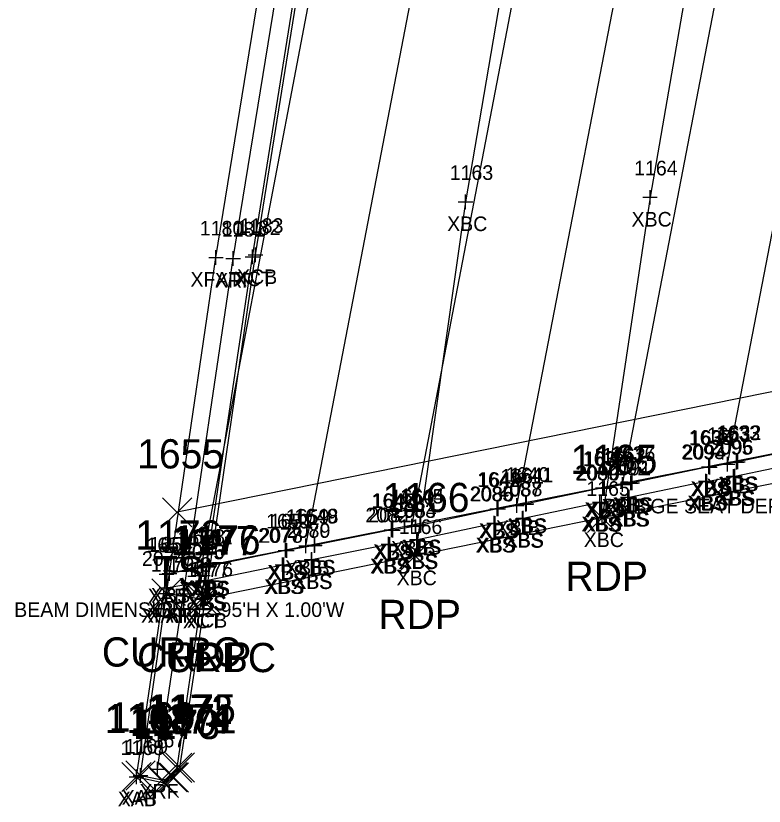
# Model space of a CAD drawing. Extents: x 1683147 to 1683637, y 416837 to 418211.
# Drawn here: x 1683191.5 to 1683242.7, y 417432.4 to 417486.5 of the extents above; entities that cross this region are included whole.
import ezdxf

# ---------------------------------------------------------------- set-up
doc = ezdxf.new("R2010")
doc.units = 0
for name, color, linetype in [('B_A', 7, 'Continuous'), ('B_C', 7, 'Continuous'), ('B_I', 7, 'Continuous'), ('B_TIC', 7, 'Continuous'), ('BB', 7, 'Continuous'), ('BDC', 7, 'Continuous'), ('BELB', 7, 'Continuous'), ('BF', 7, 'Continuous'), ('BR', 7, 'Continuous'), ('BSE', 7, 'Continuous'), ('BSUBM', 7, 'Continuous'), ('L_A', 7, 'Continuous'), ('L_I', 7, 'Continuous'), ('L_TIC', 7, 'Continuous'), ('LELB', 7, 'Continuous'), ('P_A', 7, 'Continuous'), ('P_I', 7, 'Continuous'), ('P_TIC', 7, 'Continuous'), ('PET', 7, 'Continuous'), ('R_A', 7, 'Continuous'), ('R_I', 7, 'Continuous'), ('R_TIC', 7, 'Continuous'), ('RC', 7, 'Continuous')]:
    doc.layers.add(name, color=color, linetype=linetype)

msp = doc.modelspace()

# ---------------------------------------------------------------- linework, layer by layer
at = {"layer": 'B_TIC'}
for p, q in [((1683234.935, 417474.067), (1683235.011, 417474.067)), ((1683222.32, 417473.758), (1683222.395, 417473.758)), ((1683205.244, 417469.957), (1683205.32, 417469.957)), ((1683206.416, 417469.882), (1683206.492, 417469.882)), ((1683207.749, 417469.989), (1683207.825, 417469.989)), ((1683207.946, 417470.136), (1683208.022, 417470.136)), ((1683240.227, 417455.825), (1683240.303, 417455.825)), ((1683240.858, 417455.949), (1683240.934, 417455.949)), ((1683240.939, 417455.968), (1683241.015, 417455.968)), ((1683238.962, 417455.642), (1683239.037, 417455.642)), ((1683239.038, 417455.615), (1683239.113, 417455.615)), ((1683238.747, 417454.66), (1683238.823, 417454.66)), ((1683238.823, 417454.633), (1683238.899, 417454.633)), ((1683240.644, 417454.967), (1683240.72, 417454.967)), ((1683240.729, 417454.99), (1683240.805, 417454.99)), ((1683231.708, 417454.198), (1683231.784, 417454.198)), ((1683231.818, 417454.176), (1683231.894, 417454.176)), ((1683233.059, 417454.423), (1683233.135, 417454.423)), ((1683233.626, 417454.527), (1683233.702, 417454.527)), ((1683233.723, 417454.539), (1683233.799, 417454.539)), ((1683233.417, 417453.549), (1683233.493, 417453.549)), ((1683233.51, 417453.558), (1683233.586, 417453.558)), ((1683225.821, 417452.979), (1683225.896, 417452.979)), ((1683226.435, 417453.076), (1683226.511, 417453.076)), ((1683226.483, 417453.11), (1683226.559, 417453.11)), ((1683231.494, 417453.218), (1683231.57, 417453.218)), ((1683231.605, 417453.195), (1683231.681, 417453.195)), ((1683224.476, 417452.766), (1683224.552, 417452.766)), ((1683224.555, 417452.749), (1683224.631, 417452.749)), ((1683226.223, 417452.096), (1683226.299, 417452.096)), ((1683226.268, 417452.128), (1683226.344, 417452.128)), ((1683231.664, 417452.147), (1683231.74, 417452.147)), ((1683218.643, 417451.571), (1683218.718, 417451.571)), ((1683219.203, 417451.621), (1683219.278, 417451.621)), ((1683219.252, 417451.652), (1683219.327, 417451.652)), ((1683224.267, 417451.789), (1683224.343, 417451.789)), ((1683224.341, 417451.768), (1683224.417, 417451.768)), ((1683217.258, 417451.322), (1683217.334, 417451.322)), ((1683217.34, 417451.308), (1683217.416, 417451.308)), ((1683211.977, 417450.252), (1683212.052, 417450.252)), ((1683212.015, 417450.268), (1683212.09, 417450.268)), ((1683217.043, 417450.341), (1683217.119, 417450.341)), ((1683217.133, 417450.332), (1683217.209, 417450.332)), ((1683218.988, 417450.64), (1683219.064, 417450.64)), ((1683219.037, 417450.671), (1683219.113, 417450.671)), ((1683210.009, 417449.921), (1683210.084, 417449.921)), ((1683210.085, 417449.916), (1683210.16, 417449.916)), ((1683211.401, 417450.232), (1683211.477, 417450.232)), ((1683211.768, 417449.274), (1683211.844, 417449.274)), ((1683211.801, 417449.288), (1683211.877, 417449.288)), ((1683218.866, 417449.537), (1683218.942, 417449.537)), ((1683204.011, 417448.755), (1683204.086, 417448.755)), ((1683204.251, 417448.864), (1683204.327, 417448.864)), ((1683204.726, 417448.785), (1683204.801, 417448.785)), ((1683204.787, 417448.839), (1683204.863, 417448.839)), ((1683209.794, 417448.94), (1683209.87, 417448.94)), ((1683209.876, 417448.939), (1683209.952, 417448.939)), ((1683201.862, 417448.298), (1683201.937, 417448.298)), ((1683201.862, 417448.298), (1683201.937, 417448.298)), ((1683202.059, 417448.337), (1683202.135, 417448.337)), ((1683204.517, 417447.808), (1683204.593, 417447.808)), ((1683204.574, 417447.86), (1683204.65, 417447.86)), ((1683201.846, 417447.358), (1683201.922, 417447.358)), ((1683201.856, 417446.968), (1683201.931, 417446.968)), ((1683201.856, 417446.968), (1683201.931, 417446.968)), ((1683203.022, 417446.95), (1683203.098, 417446.95)), ((1683204.263, 417446.59), (1683204.339, 417446.59)), ((1683204.527, 417446.635), (1683204.602, 417446.635)), ((1683201.253, 417434.944), (1683201.328, 417434.944)), ((1683199.805, 417434.421), (1683199.88, 417434.421)), ((1683200.088, 417434.523), (1683200.163, 417434.523))]:
    msp.add_line(p, q, dxfattribs=at)
for points in [[(1683222.317, 417473.258), (1683222.317, 417474.258)], [(1683234.432, 417474.067), (1683235.432, 417474.067)], [(1683234.932, 417473.567), (1683234.932, 417474.567)], [(1683221.817, 417473.758), (1683222.817, 417473.758)], [(1683205.241, 417469.457), (1683205.241, 417470.457)], [(1683206.413, 417469.382), (1683206.413, 417470.382)], [(1683207.746, 417469.489), (1683207.746, 417470.489)], [(1683207.943, 417469.636), (1683207.943, 417470.636)], [(1683204.741, 417469.957), (1683205.741, 417469.957)], [(1683205.913, 417469.882), (1683206.913, 417469.882)], [(1683207.246, 417469.989), (1683208.246, 417469.989)], [(1683207.443, 417470.136), (1683208.443, 417470.136)], [(1683240.224, 417455.325), (1683240.224, 417456.325)], [(1683240.855, 417455.449), (1683240.855, 417456.449)], [(1683240.936, 417455.468), (1683240.936, 417456.468)], [(1683238.958, 417455.142), (1683238.958, 417456.142)], [(1683239.034, 417455.115), (1683239.034, 417456.115)], [(1683239.724, 417455.825), (1683240.724, 417455.825)], [(1683240.355, 417455.949), (1683241.355, 417455.949)], [(1683240.436, 417455.968), (1683241.436, 417455.968)], [(1683238.458, 417455.642), (1683239.458, 417455.642)], [(1683238.534, 417455.615), (1683239.534, 417455.615)], [(1683238.744, 417454.16), (1683238.744, 417455.16)], [(1683238.82, 417454.133), (1683238.82, 417455.133)], [(1683240.641, 417454.467), (1683240.641, 417455.467)], [(1683240.726, 417454.49), (1683240.726, 417455.49)], [(1683231.705, 417453.698), (1683231.705, 417454.698)], [(1683231.815, 417453.676), (1683231.815, 417454.676)], [(1683233.056, 417453.923), (1683233.056, 417454.923)], [(1683233.623, 417454.027), (1683233.623, 417455.027)], [(1683233.72, 417454.039), (1683233.72, 417455.039)], [(1683238.244, 417454.66), (1683239.244, 417454.66)], [(1683238.32, 417454.633), (1683239.32, 417454.633)], [(1683240.141, 417454.967), (1683241.141, 417454.967)], [(1683240.226, 417454.99), (1683241.226, 417454.99)], [(1683231.205, 417454.198), (1683232.205, 417454.198)], [(1683231.315, 417454.176), (1683232.315, 417454.176)], [(1683232.556, 417454.423), (1683233.556, 417454.423)], [(1683233.123, 417454.527), (1683234.123, 417454.527)], [(1683233.22, 417454.539), (1683234.22, 417454.539)], [(1683233.414, 417453.049), (1683233.414, 417454.049)], [(1683233.507, 417453.058), (1683233.507, 417454.058)], [(1683226.432, 417452.576), (1683226.432, 417453.576)], [(1683226.48, 417452.61), (1683226.48, 417453.61)], [(1683231.491, 417452.718), (1683231.491, 417453.718)], [(1683231.602, 417452.695), (1683231.602, 417453.695)], [(1683232.914, 417453.549), (1683233.914, 417453.549)], [(1683233.007, 417453.558), (1683234.007, 417453.558)], [(1683224.473, 417452.266), (1683224.473, 417453.266)], [(1683224.552, 417452.249), (1683224.552, 417453.249)], [(1683225.317, 417452.979), (1683226.317, 417452.979)], [(1683225.817, 417452.479), (1683225.817, 417453.479)], [(1683225.932, 417453.076), (1683226.932, 417453.076)], [(1683225.98, 417453.11), (1683226.98, 417453.11)], [(1683230.991, 417453.218), (1683231.991, 417453.218)], [(1683231.102, 417453.195), (1683232.102, 417453.195)], [(1683223.973, 417452.766), (1683224.973, 417452.766)], [(1683224.052, 417452.749), (1683225.052, 417452.749)], [(1683226.22, 417451.596), (1683226.22, 417452.596)], [(1683226.265, 417451.628), (1683226.265, 417452.628)], [(1683231.661, 417451.647), (1683231.661, 417452.647)], [(1683218.639, 417451.071), (1683218.639, 417452.071)], [(1683219.199, 417451.121), (1683219.199, 417452.121)], [(1683219.248, 417451.152), (1683219.248, 417452.152)], [(1683224.264, 417451.289), (1683224.264, 417452.289)], [(1683224.338, 417451.268), (1683224.338, 417452.268)], [(1683225.72, 417452.096), (1683226.72, 417452.096)], [(1683225.765, 417452.128), (1683226.765, 417452.128)], [(1683231.161, 417452.147), (1683232.161, 417452.147)], [(1683217.255, 417450.822), (1683217.255, 417451.822)], [(1683217.337, 417450.808), (1683217.337, 417451.808)], [(1683218.139, 417451.571), (1683219.139, 417451.571)], [(1683218.699, 417451.621), (1683219.699, 417451.621)], [(1683218.748, 417451.652), (1683219.748, 417451.652)], [(1683223.764, 417451.789), (1683224.764, 417451.789)], [(1683223.838, 417451.768), (1683224.838, 417451.768)], [(1683216.755, 417451.322), (1683217.755, 417451.322)], [(1683216.837, 417451.308), (1683217.837, 417451.308)], [(1683217.04, 417449.841), (1683217.04, 417450.841)], [(1683217.13, 417449.832), (1683217.13, 417450.832)], [(1683218.985, 417450.14), (1683218.985, 417451.14)], [(1683219.034, 417450.171), (1683219.034, 417451.171)], [(1683210.005, 417449.421), (1683210.005, 417450.421)], [(1683210.081, 417449.416), (1683210.081, 417450.416)], [(1683211.398, 417449.732), (1683211.398, 417450.732)], [(1683211.473, 417450.252), (1683212.473, 417450.252)], [(1683211.511, 417450.268), (1683212.511, 417450.268)], [(1683211.973, 417449.752), (1683211.973, 417450.752)], [(1683212.011, 417449.768), (1683212.011, 417450.768)], [(1683216.54, 417450.341), (1683217.54, 417450.341)], [(1683216.63, 417450.332), (1683217.63, 417450.332)], [(1683218.485, 417450.64), (1683219.485, 417450.64)], [(1683218.534, 417450.671), (1683219.534, 417450.671)], [(1683209.505, 417449.921), (1683210.505, 417449.921)], [(1683209.581, 417449.916), (1683210.581, 417449.916)], [(1683210.898, 417450.232), (1683211.898, 417450.232)], [(1683211.765, 417448.774), (1683211.765, 417449.774)], [(1683211.798, 417448.788), (1683211.798, 417449.788)], [(1683218.863, 417449.037), (1683218.863, 417450.037)], [(1683204.007, 417448.255), (1683204.007, 417449.255)], [(1683204.248, 417448.364), (1683204.248, 417449.364)], [(1683204.722, 417448.285), (1683204.722, 417449.285)], [(1683204.784, 417448.339), (1683204.784, 417449.339)], [(1683209.791, 417448.44), (1683209.791, 417449.44)], [(1683209.873, 417448.439), (1683209.873, 417449.439)], [(1683211.265, 417449.274), (1683212.265, 417449.274)], [(1683211.298, 417449.288), (1683212.298, 417449.288)], [(1683218.363, 417449.537), (1683219.363, 417449.537)], [(1683201.858, 417447.798), (1683201.858, 417448.798)], [(1683201.858, 417447.798), (1683201.858, 417448.798)], [(1683202.056, 417447.837), (1683202.056, 417448.837)], [(1683203.507, 417448.755), (1683204.507, 417448.755)], [(1683203.748, 417448.864), (1683204.748, 417448.864)], [(1683204.222, 417448.785), (1683205.222, 417448.785)], [(1683204.284, 417448.839), (1683205.284, 417448.839)], [(1683209.291, 417448.94), (1683210.291, 417448.94)], [(1683209.373, 417448.939), (1683210.373, 417448.939)], [(1683201.358, 417448.298), (1683202.358, 417448.298)], [(1683201.358, 417448.298), (1683202.358, 417448.298)], [(1683201.556, 417448.337), (1683202.556, 417448.337)], [(1683204.514, 417447.308), (1683204.514, 417448.308)], [(1683204.571, 417447.36), (1683204.571, 417448.36)], [(1683201.843, 417446.858), (1683201.843, 417447.858)], [(1683204.014, 417447.808), (1683205.014, 417447.808)], [(1683204.071, 417447.86), (1683205.071, 417447.86)], [(1683201.343, 417447.358), (1683202.343, 417447.358)], [(1683201.852, 417446.468), (1683201.852, 417447.468)], [(1683201.852, 417446.468), (1683201.852, 417447.468)], [(1683203.019, 417446.45), (1683203.019, 417447.45)], [(1683204.26, 417446.09), (1683204.26, 417447.09)], [(1683204.523, 417446.135), (1683204.523, 417447.135)], [(1683201.352, 417446.968), (1683202.352, 417446.968)], [(1683201.352, 417446.968), (1683202.352, 417446.968)], [(1683202.519, 417446.95), (1683203.519, 417446.95)], [(1683203.76, 417446.59), (1683204.76, 417446.59)], [(1683204.023, 417446.635), (1683205.023, 417446.635)], [(1683201.249, 417434.444), (1683201.249, 417435.444)], [(1683199.801, 417433.921), (1683199.801, 417434.921)], [(1683200.084, 417434.023), (1683200.084, 417435.023)], [(1683200.749, 417434.944), (1683201.749, 417434.944)], [(1683199.301, 417434.421), (1683200.301, 417434.421)], [(1683199.584, 417434.523), (1683200.584, 417434.523)]]:
    msp.add_lwpolyline(points, dxfattribs=at)
at = {"layer": 'BB'}
for points in [[(1683240.224, 417455.825), (1683249.612, 417504.3), (1683268.309, 417601.755), (1683277.362, 417650.167)], [(1683233.056, 417454.423), (1683242.375, 417502.873), (1683260.963, 417600.277), (1683270.09, 417648.672)], [(1683225.817, 417452.979), (1683235.185, 417501.44), (1683252.981, 417597.315), (1683262.91, 417647.271)], [(1683218.639, 417451.571), (1683227.942, 417499.995), (1683246.282, 417596.559), (1683255.565, 417645.821)], [(1683211.398, 417450.232), (1683220.685, 417498.601), (1683239.091, 417595.537), (1683248.339, 417644.482)], [(1683204.248, 417448.864), (1683213.453, 417497.213), (1683232.034, 417594.621), (1683241.123, 417643.096)]]:
    msp.add_lwpolyline(points, dxfattribs=at)
at = {"layer": 'BDC'}
for points in [[(1683204.26, 417446.59), (1683207.746, 417469.989), (1683213.462, 417505.801), (1683221.311, 417549.93), (1683228.046, 417584.722), (1683234.074, 417613.621), (1683241.065, 417645.18)], [(1683204.523, 417446.635), (1683207.943, 417470.136), (1683213.692, 417505.86), (1683221.542, 417549.946), (1683228.342, 417584.807), (1683234.248, 417613.515), (1683241.392, 417644.923)]]:
    msp.add_lwpolyline(points, dxfattribs=at)
at = {"layer": 'BELB'}
for points in [[(1683269.206, 417650.948), (1683260.393, 417611.397), (1683256.447, 417590.785), (1683246.822, 417543.339), (1683241.399, 417511.39), (1683234.932, 417474.067), (1683231.661, 417452.147)], [(1683255.821, 417648.166), (1683248.035, 417613.702), (1683243.06, 417587.805), (1683234.781, 417546.02), (1683228.274, 417508.761), (1683222.317, 417473.758), (1683218.863, 417449.537)]]:
    msp.add_lwpolyline(points, dxfattribs=at)
at = {"layer": 'BF'}
msp.add_lwpolyline([(1683201.852, 417446.968), (1683205.241, 417469.957), (1683210.957, 417505.098), (1683219.149, 417550.319), (1683225.494, 417584.011), (1683231.655, 417613.999), (1683238.79, 417645.736)], dxfattribs=at)
at = {"layer": 'BR'}
msp.add_lwpolyline([(1683201.249, 417434.944), (1683203.019, 417446.95), (1683206.413, 417469.882), (1683212.207, 417505.421), (1683220.042, 417550.002), (1683226.73, 417584.319), (1683232.917, 417613.974), (1683239.772, 417645.191), (1683242.155, 417655.448)], dxfattribs=at)
at = {"layer": 'BSE'}
msp.add_lwpolyline([(1683246.189, 417457.073), (1683240.936, 417455.968), (1683240.855, 417455.949), (1683239.034, 417455.615), (1683238.958, 417455.642), (1683233.72, 417454.539), (1683233.623, 417454.527), (1683231.815, 417454.176), (1683231.705, 417454.198), (1683226.48, 417453.11), (1683226.432, 417453.076), (1683224.552, 417452.749), (1683224.473, 417452.766), (1683219.248, 417451.652), (1683219.199, 417451.621), (1683217.337, 417451.308), (1683217.255, 417451.322), (1683212.011, 417450.268), (1683211.973, 417450.252), (1683210.081, 417449.916), (1683210.005, 417449.921), (1683204.784, 417448.839), (1683204.722, 417448.785), (1683202.056, 417448.337), (1683201.843, 417447.358), (1683204.514, 417447.808), (1683204.571, 417447.86), (1683209.791, 417448.94), (1683209.873, 417448.939), (1683211.765, 417449.274), (1683211.798, 417449.288), (1683217.04, 417450.341), (1683217.13, 417450.332), (1683218.985, 417450.64), (1683219.034, 417450.671), (1683224.264, 417451.789), (1683224.338, 417451.768), (1683226.22, 417452.096), (1683226.265, 417452.128), (1683231.491, 417453.218), (1683231.602, 417453.195), (1683233.414, 417453.549), (1683233.507, 417453.558), (1683238.744, 417454.66), (1683238.82, 417454.633), (1683240.641, 417454.967), (1683240.726, 417454.99), (1683245.982, 417456.097)], dxfattribs=at)
at = {"layer": 'BSUBM'}
for points in [[(1683249.739, 417447.724), (1683250.343, 417451.889), (1683251.139, 417457.637), (1683249.956, 417457.826), (1683204.007, 417448.755), (1683201.858, 417448.298)], [(1683199.801, 417434.421), (1683201.858, 417448.298)], [(1683200.084, 417434.523), (1683201.852, 417446.968)]]:
    msp.add_lwpolyline(points, dxfattribs=at)
at = {"layer": 'L_TIC'}
for points in [[(1683201.589, 417451.523), (1683203.589, 417453.523)], [(1683203.589, 417451.523), (1683201.589, 417453.523)], [(1683201.776, 417434.074), (1683203.776, 417436.074)], [(1683203.776, 417434.074), (1683201.776, 417436.074)], [(1683198.801, 417433.421), (1683200.801, 417435.421)], [(1683200.801, 417433.421), (1683198.801, 417435.421)], [(1683201.371, 417433.382), (1683203.371, 417435.382)], [(1683203.371, 417433.382), (1683201.371, 417435.382)], [(1683200.687, 417433.013), (1683202.687, 417435.013)], [(1683202.687, 417433.013), (1683200.687, 417435.013)]]:
    msp.add_lwpolyline(points, dxfattribs=at)
at = {"layer": 'LELB'}
for points in [[(1683250.588, 417462.234), (1683202.589, 417452.523)], [(1683199.801, 417434.421), (1683201.687, 417434.013), (1683202.371, 417434.382), (1683202.776, 417435.074)]]:
    msp.add_lwpolyline(points, dxfattribs=at)
at = {"layer": 'P_TIC'}
for points in [[(1683230.661, 417451.147), (1683232.661, 417453.147)], [(1683232.661, 417451.147), (1683230.661, 417453.147)], [(1683217.863, 417448.537), (1683219.863, 417450.537)], [(1683219.863, 417448.537), (1683217.863, 417450.537)], [(1683203.523, 417445.635), (1683205.523, 417447.635)], [(1683205.523, 417445.635), (1683203.523, 417447.635)], [(1683203.523, 417445.635), (1683205.523, 417447.635)], [(1683205.523, 417445.635), (1683203.523, 417447.635)], [(1683201.776, 417434.074), (1683203.776, 417436.074)], [(1683203.776, 417434.074), (1683201.776, 417436.074)]]:
    msp.add_lwpolyline(points, dxfattribs=at)
at = {"layer": 'PET'}
for points in [[(1683247.055, 417449.157), (1683248.051, 417455.436), (1683231.661, 417452.147), (1683218.863, 417449.537), (1683204.523, 417446.635)], [(1683202.776, 417435.074), (1683204.523, 417446.635)]]:
    msp.add_lwpolyline(points, dxfattribs=at)
at = {"layer": 'R_TIC'}
for points in [[(1683200.852, 417445.968), (1683202.852, 417447.968)], [(1683202.852, 417445.968), (1683200.852, 417447.968)], [(1683203.26, 417445.59), (1683205.26, 417447.59)], [(1683205.26, 417445.59), (1683203.26, 417447.59)], [(1683201.581, 417434.047), (1683203.581, 417436.047)], [(1683203.581, 417434.047), (1683201.581, 417436.047)], [(1683199.084, 417433.523), (1683201.084, 417435.523)], [(1683201.084, 417433.523), (1683199.084, 417435.523)], [(1683200.551, 417433.231), (1683202.551, 417435.231)], [(1683202.551, 417433.231), (1683200.551, 417435.231)], [(1683201.263, 417433.402), (1683203.263, 417435.402)], [(1683203.263, 417433.402), (1683201.263, 417435.402)]]:
    msp.add_lwpolyline(points, dxfattribs=at)
at = {"layer": 'RC'}
msp.add_lwpolyline([(1683200.084, 417434.523), (1683201.551, 417434.231), (1683202.263, 417434.402), (1683202.581, 417435.047), (1683204.26, 417446.59), (1683201.852, 417446.968)], dxfattribs=at)

# ---------------------------------------------------------------- texts
at = {"layer": 'B_A'}
for s, p in [('XBC', (1683233.668, 417472.067)), ('XBC', (1683221.053, 417471.758)), ('XFAT', (1683203.497, 417467.957)), ('XRF', (1683205.172, 417467.882)), ('XCT', (1683206.466, 417467.989)), ('XCB', (1683206.679, 417468.136)), ('XBS', (1683237.698, 417453.642)), ('XBS', (1683237.775, 417453.615)), ('XBIB', (1683238.794, 417453.825)), ('XBS', (1683239.595, 417453.949)), ('XBS', (1683239.676, 417453.968)), ('XBS', (1683232.363, 417452.527)), ('XBS', (1683232.46, 417452.539)), ('XBS', (1683237.484, 417452.66)), ('XBS', (1683237.56, 417452.633)), ('XBS', (1683239.381, 417452.967)), ('XBS', (1683239.466, 417452.99)), ('XBS', (1683230.445, 417452.198)), ('XBS', (1683230.555, 417452.176)), ('XBIB', (1683231.627, 417452.423)), ('XBS', (1683232.154, 417451.549)), ('XBS', (1683232.247, 417451.558)), ('XBIB', (1683224.388, 417450.979)), ('XBS', (1683225.172, 417451.076)), ('XBS', (1683225.22, 417451.11)), ('XBS', (1683230.231, 417451.218)), ('XBS', (1683230.342, 417451.195)), ('XBS', (1683223.213, 417450.766)), ('XBS', (1683223.292, 417450.749)), ('XBS', (1683223.004, 417449.789)), ('XBS', (1683224.96, 417450.096)), ('XBS', (1683225.005, 417450.128)), ('XBC', (1683230.397, 417450.147)), ('XBS', (1683215.995, 417449.322)), ('XBS', (1683216.077, 417449.308)), ('XBIB', (1683217.21, 417449.571)), ('XBS', (1683217.939, 417449.621)), ('XBS', (1683217.989, 417449.652)), ('XBS', (1683223.078, 417449.768)), ('XBIB', (1683209.969, 417448.232)), ('XBS', (1683210.714, 417448.252)), ('XBS', (1683210.751, 417448.268)), ('XBS', (1683215.78, 417448.341)), ('XBS', (1683215.87, 417448.332)), ('XBS', (1683217.725, 417448.64)), ('XBS', (1683217.774, 417448.671)), ('XBS', (1683208.746, 417447.921)), ('XBS', (1683208.822, 417447.916)), ('XBS', (1683210.505, 417447.274)), ('XBS', (1683210.538, 417447.288)), ('XBC', (1683217.599, 417447.537)), ('XAB', (1683202.728, 417446.755)), ('XBIB', (1683202.819, 417446.864)), ('XBS', (1683203.462, 417446.785)), ('XBS', (1683203.524, 417446.839)), ('XBS', (1683208.531, 417446.94)), ('XBS', (1683208.613, 417446.939)), ('XAB', (1683200.579, 417446.298)), ('XAB', (1683200.579, 417446.298)), ('XBS', (1683200.796, 417446.337)), ('XBS', (1683203.254, 417445.808)), ('XBS', (1683203.311, 417445.86)), ('XFAT', (1683200.108, 417444.968)), ('XAT', (1683200.557, 417444.968)), ('XBS', (1683200.583, 417445.358)), ('XRF', (1683201.779, 417444.95)), ('XCT', (1683202.98, 417444.59)), ('XCB', (1683203.26, 417444.635)), ('XAT', (1683198.789, 417432.523)), ('XRF', (1683200.009, 417432.944)), ('XAB', (1683198.522, 417432.421))]:
    msp.add_text(s, height=1, dxfattribs=at).set_placement(p)
at = {"layer": 'B_C'}
for s, p in [("BRIDGE SEAT DEPTH 1.0'", (1683231.761, 417452.449)), ("BEAM DIMENSIONS 2.95'H X 1.00'W", (1683191.437, 417445.364))]:
    msp.add_text(s, height=1, dxfattribs=at).set_placement(p)
at = {"layer": 'B_I'}
for s, p in [('1163', (1683221.23, 417475.258)), ('1164', (1683233.845, 417475.567)), ('1180', (1683204.134, 417471.457)), ('1182', (1683206.683, 417471.489)), ('1183', (1683206.88, 417471.636)), ('1181', (1683205.633, 417471.382)), ('1633', (1683239.485, 417457.449)), ('1632', (1683239.566, 417457.468)), ('1635', (1683237.588, 417457.142)), ('1634', (1683237.664, 417457.115)), ('1663', (1683238.83, 417457.325)), ('2095', (1683238.972, 417456.467)), ('2096', (1683239.029, 417456.49)), ('1662', (1683231.662, 417455.923)), ('1637', (1683232.253, 417456.027)), ('1636', (1683232.322, 417456.039)), ('2093', (1683237.075, 417456.16)), ('2094', (1683237.151, 417456.133)), ('1639', (1683230.331, 417455.698)), ('1638', (1683230.445, 417455.676)), ('2089', (1683229.818, 417454.718)), ('2090', (1683229.889, 417454.695)), ('2092', (1683231.838, 417455.058)), ('2091', (1683232.028, 417455.049)), ('1643', (1683223.103, 417454.266)), ('1642', (1683223.182, 417454.249)), ('1661', (1683224.707, 417454.479)), ('1640', (1683225.066, 417454.61)), ('1641', (1683225.345, 417454.576)), ('2087', (1683224.551, 417453.596)), ('2088', (1683224.596, 417453.628)), ('1165', (1683230.574, 417453.647)), ('1660', (1683217.202, 417453.071)), ('1645', (1683217.829, 417453.121)), ('1644', (1683217.878, 417453.152)), ('2085', (1683222.595, 417453.289)), ('2086', (1683222.641, 417453.268)), ('1647', (1683215.885, 417452.822)), ('1646', (1683215.939, 417452.808)), ('2083', (1683217.316, 417452.14)), ('2084', (1683217.365, 417452.171)), ('1650', (1683208.668, 417451.416)), ('1651', (1683208.919, 417451.421)), ('1659', (1683210.024, 417451.732)), ('1649', (1683210.599, 417451.752)), ('1648', (1683210.641, 417451.768)), ('2082', (1683215.461, 417451.832)), ('2081', (1683215.654, 417451.841)), ('1166', (1683217.749, 417451.037)), ('1658', (1683202.878, 417450.364)), ('1652', (1683203.414, 417450.339)), ('2077', (1683208.122, 417450.44)), ('2078', (1683208.204, 417450.439)), ('2080', (1683210.085, 417450.788)), ('2079', (1683210.092, 417450.774)), ('1657', (1683200.488, 417449.798)), ('1657', (1683200.488, 417449.798)), ('1654', (1683200.686, 417449.837)), ('1656', (1683202.61, 417450.255)), ('1653', (1683203.352, 417450.285)), ('2075', (1683202.845, 417449.308)), ('2076', (1683202.874, 417449.36)), ('2074', (1683200.174, 417448.858)), ('1179', (1683200.786, 417448.468)), ('1179', (1683200.786, 417448.468)), ('1178', (1683201.956, 417448.45)), ('1177', (1683203.197, 417448.09)), ('1176', (1683203.433, 417448.135)), ('1167', (1683200.163, 417436.444)), ('1168', (1683198.715, 417435.921)), ('1169', (1683198.994, 417436.023))]:
    msp.add_text(s, height=1, dxfattribs=at).set_placement(p)
at = {"layer": 'L_A'}
msp.add_text('TS', height=2, dxfattribs=at).set_placement((1683200.998, 417447.523))
at = {"layer": 'L_I'}
for s, p in [('1655', (1683199.849, 417455.523)), ('1175', (1683200.65, 417438.074)), ('1168', (1683197.628, 417437.421)), ('1173', (1683199.561, 417437.013)), ('1174', (1683200.246, 417437.382))]:
    msp.add_text(s, height=2, dxfattribs=at).set_placement(p)
at = {"layer": 'P_A'}
for p in [(1683229.149, 417447.147), (1683216.351, 417444.537), (1683202.012, 417441.635), (1683202.012, 417441.635)]:
    msp.add_text('RDP', height=2, dxfattribs=at).set_placement(p)
at = {"layer": 'P_I'}
for s, p in [('1165', (1683229.488, 417455.147)), ('1166', (1683216.635, 417452.537)), ('1176', (1683202.343, 417449.635)), ('1176', (1683202.343, 417449.635)), ('1175', (1683200.65, 417438.074))]:
    msp.add_text(s, height=2, dxfattribs=at).set_placement(p)
at = {"layer": 'R_A'}
for p in [(1683197.435, 417441.968), (1683199.842, 417441.59)]:
    msp.add_text('CURBC', height=2, dxfattribs=at).set_placement(p)
at = {"layer": 'R_I'}
for s, p in [('1179', (1683199.719, 417449.968)), ('1177', (1683202.134, 417449.59)), ('1172', (1683200.455, 417438.047)), ('1169', (1683197.903, 417437.523)), ('1170', (1683199.338, 417437.231)), ('1171', (1683200.704, 417437.402))]:
    msp.add_text(s, height=2, dxfattribs=at).set_placement(p)

doc.saveas('drawing.dxf')
